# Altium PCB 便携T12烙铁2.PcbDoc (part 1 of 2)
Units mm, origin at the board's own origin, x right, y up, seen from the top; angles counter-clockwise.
Board outline 100 x 95 mm, 2 copper layers (Top Layer, Bottom Layer); 155 components, 22 nets, 605 pads, 185 vias.
Unrouted connection lines stored in the file: 84.
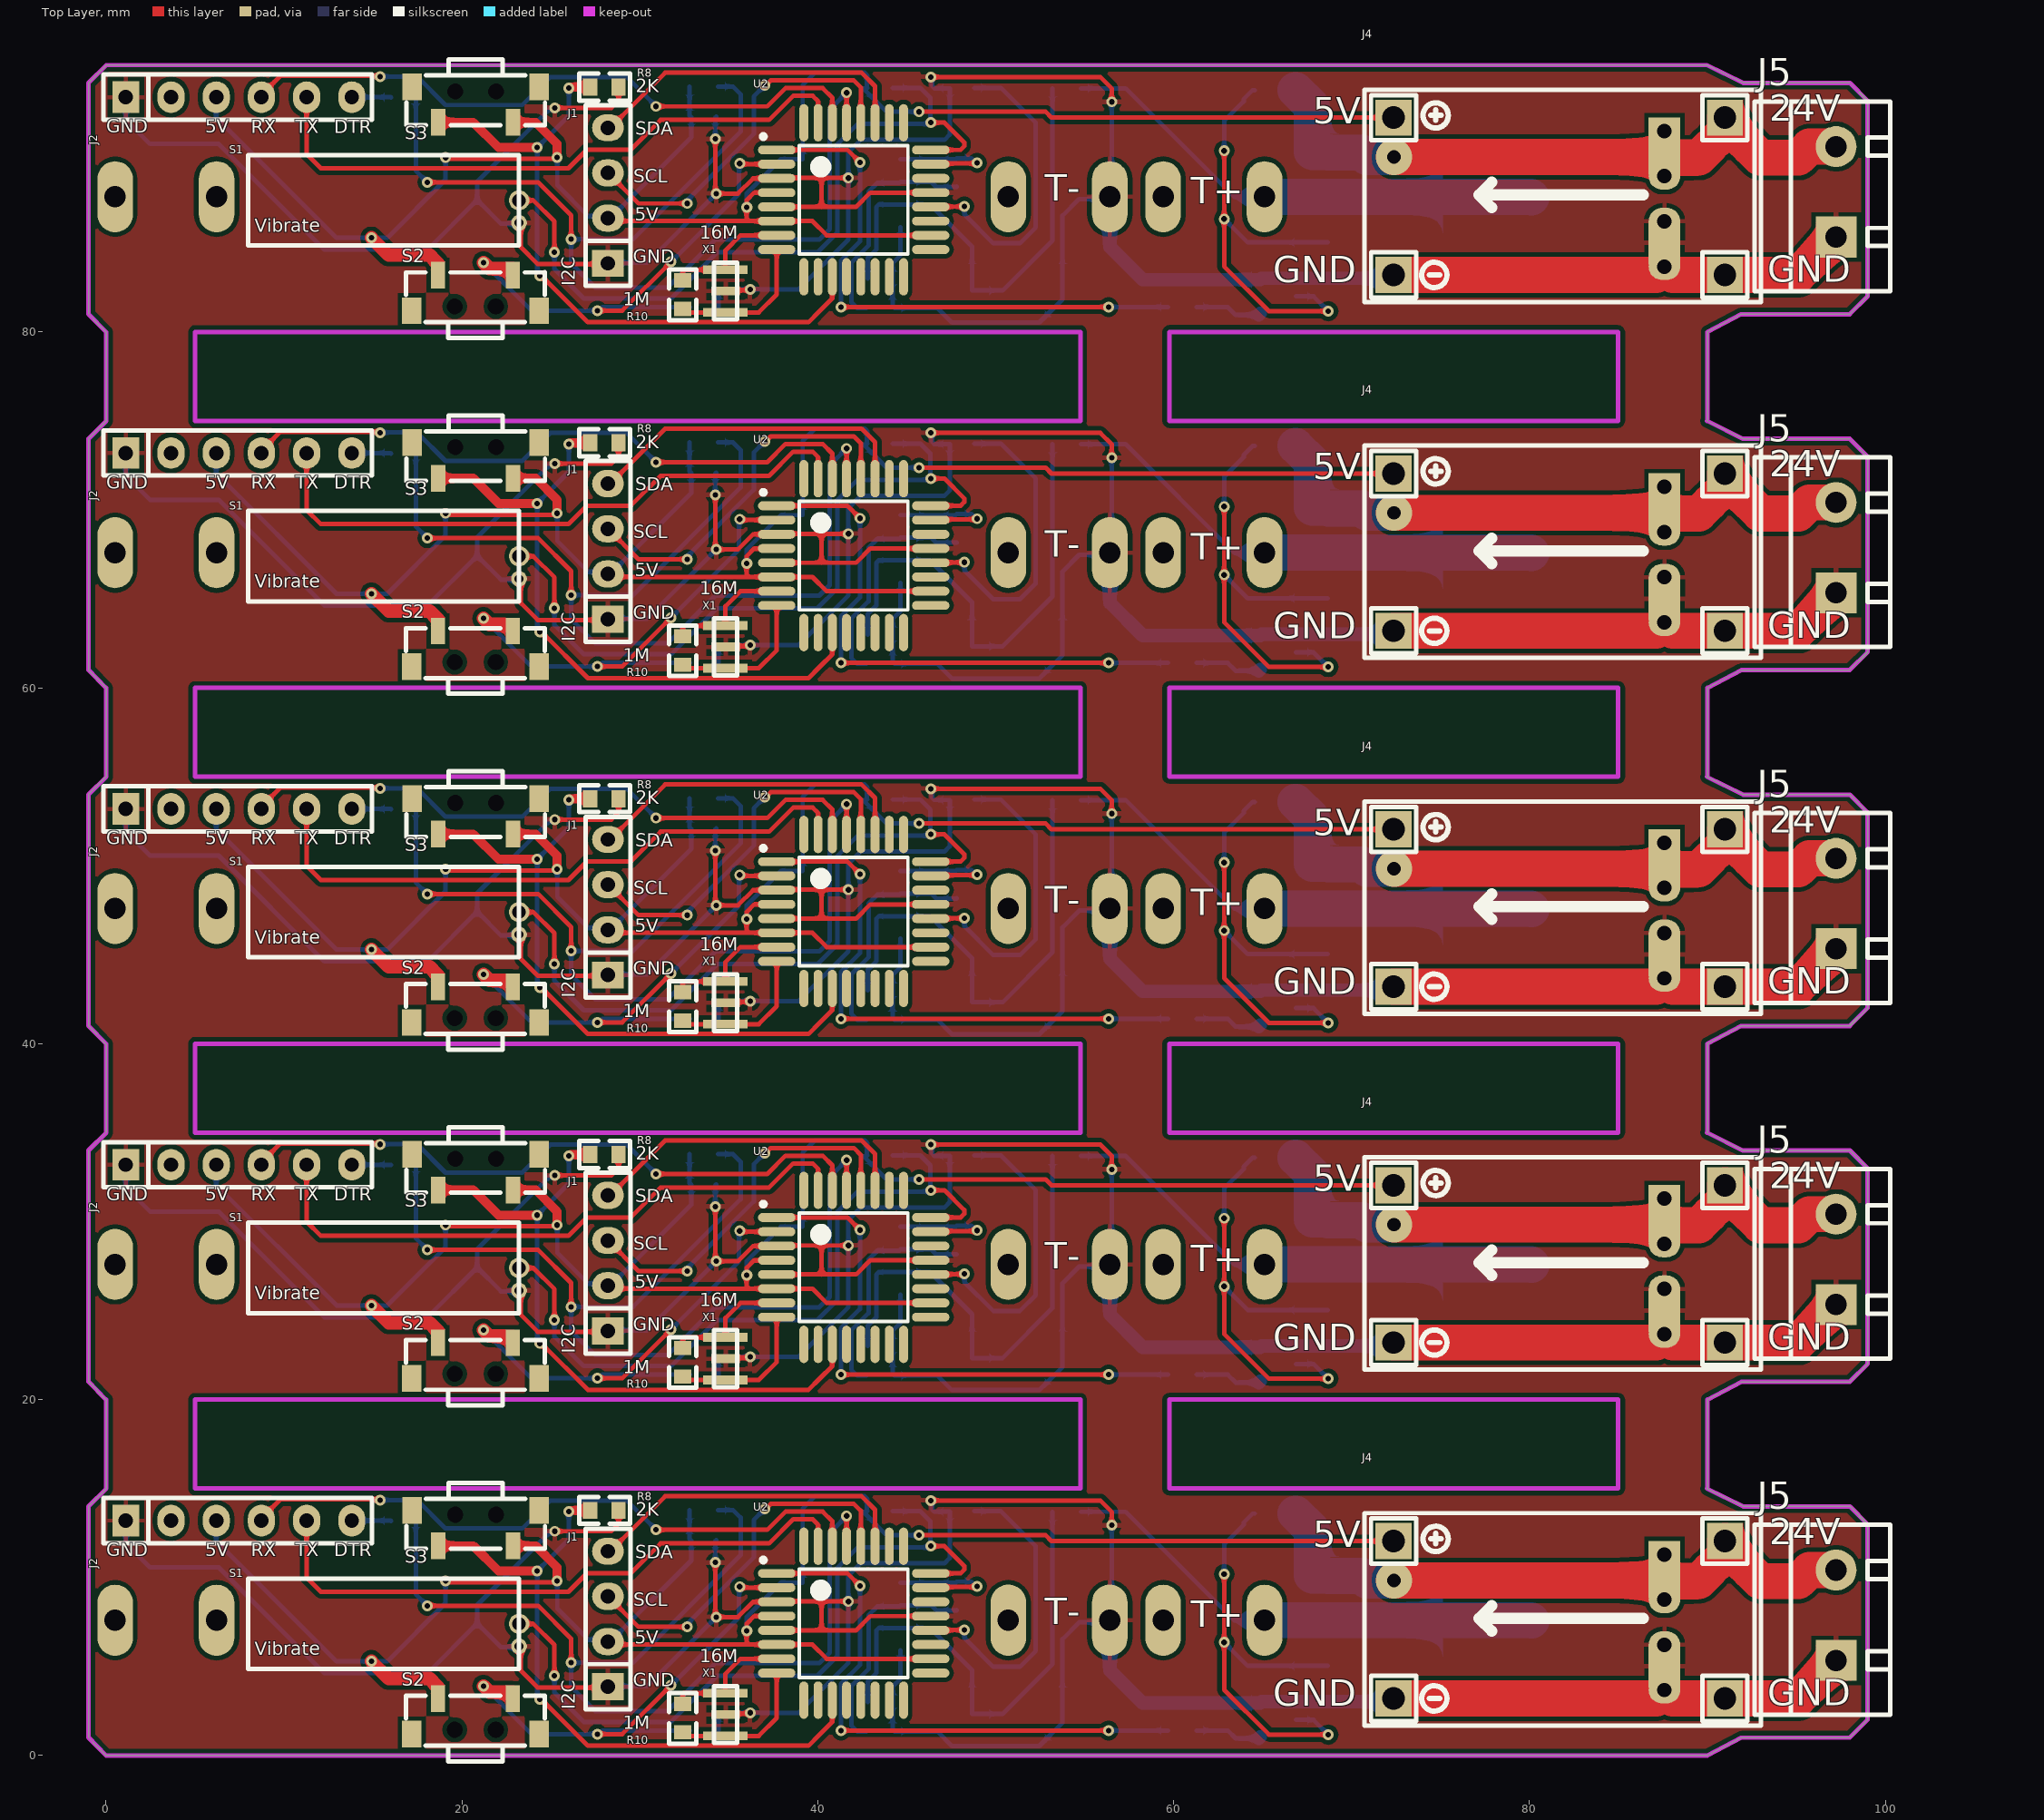
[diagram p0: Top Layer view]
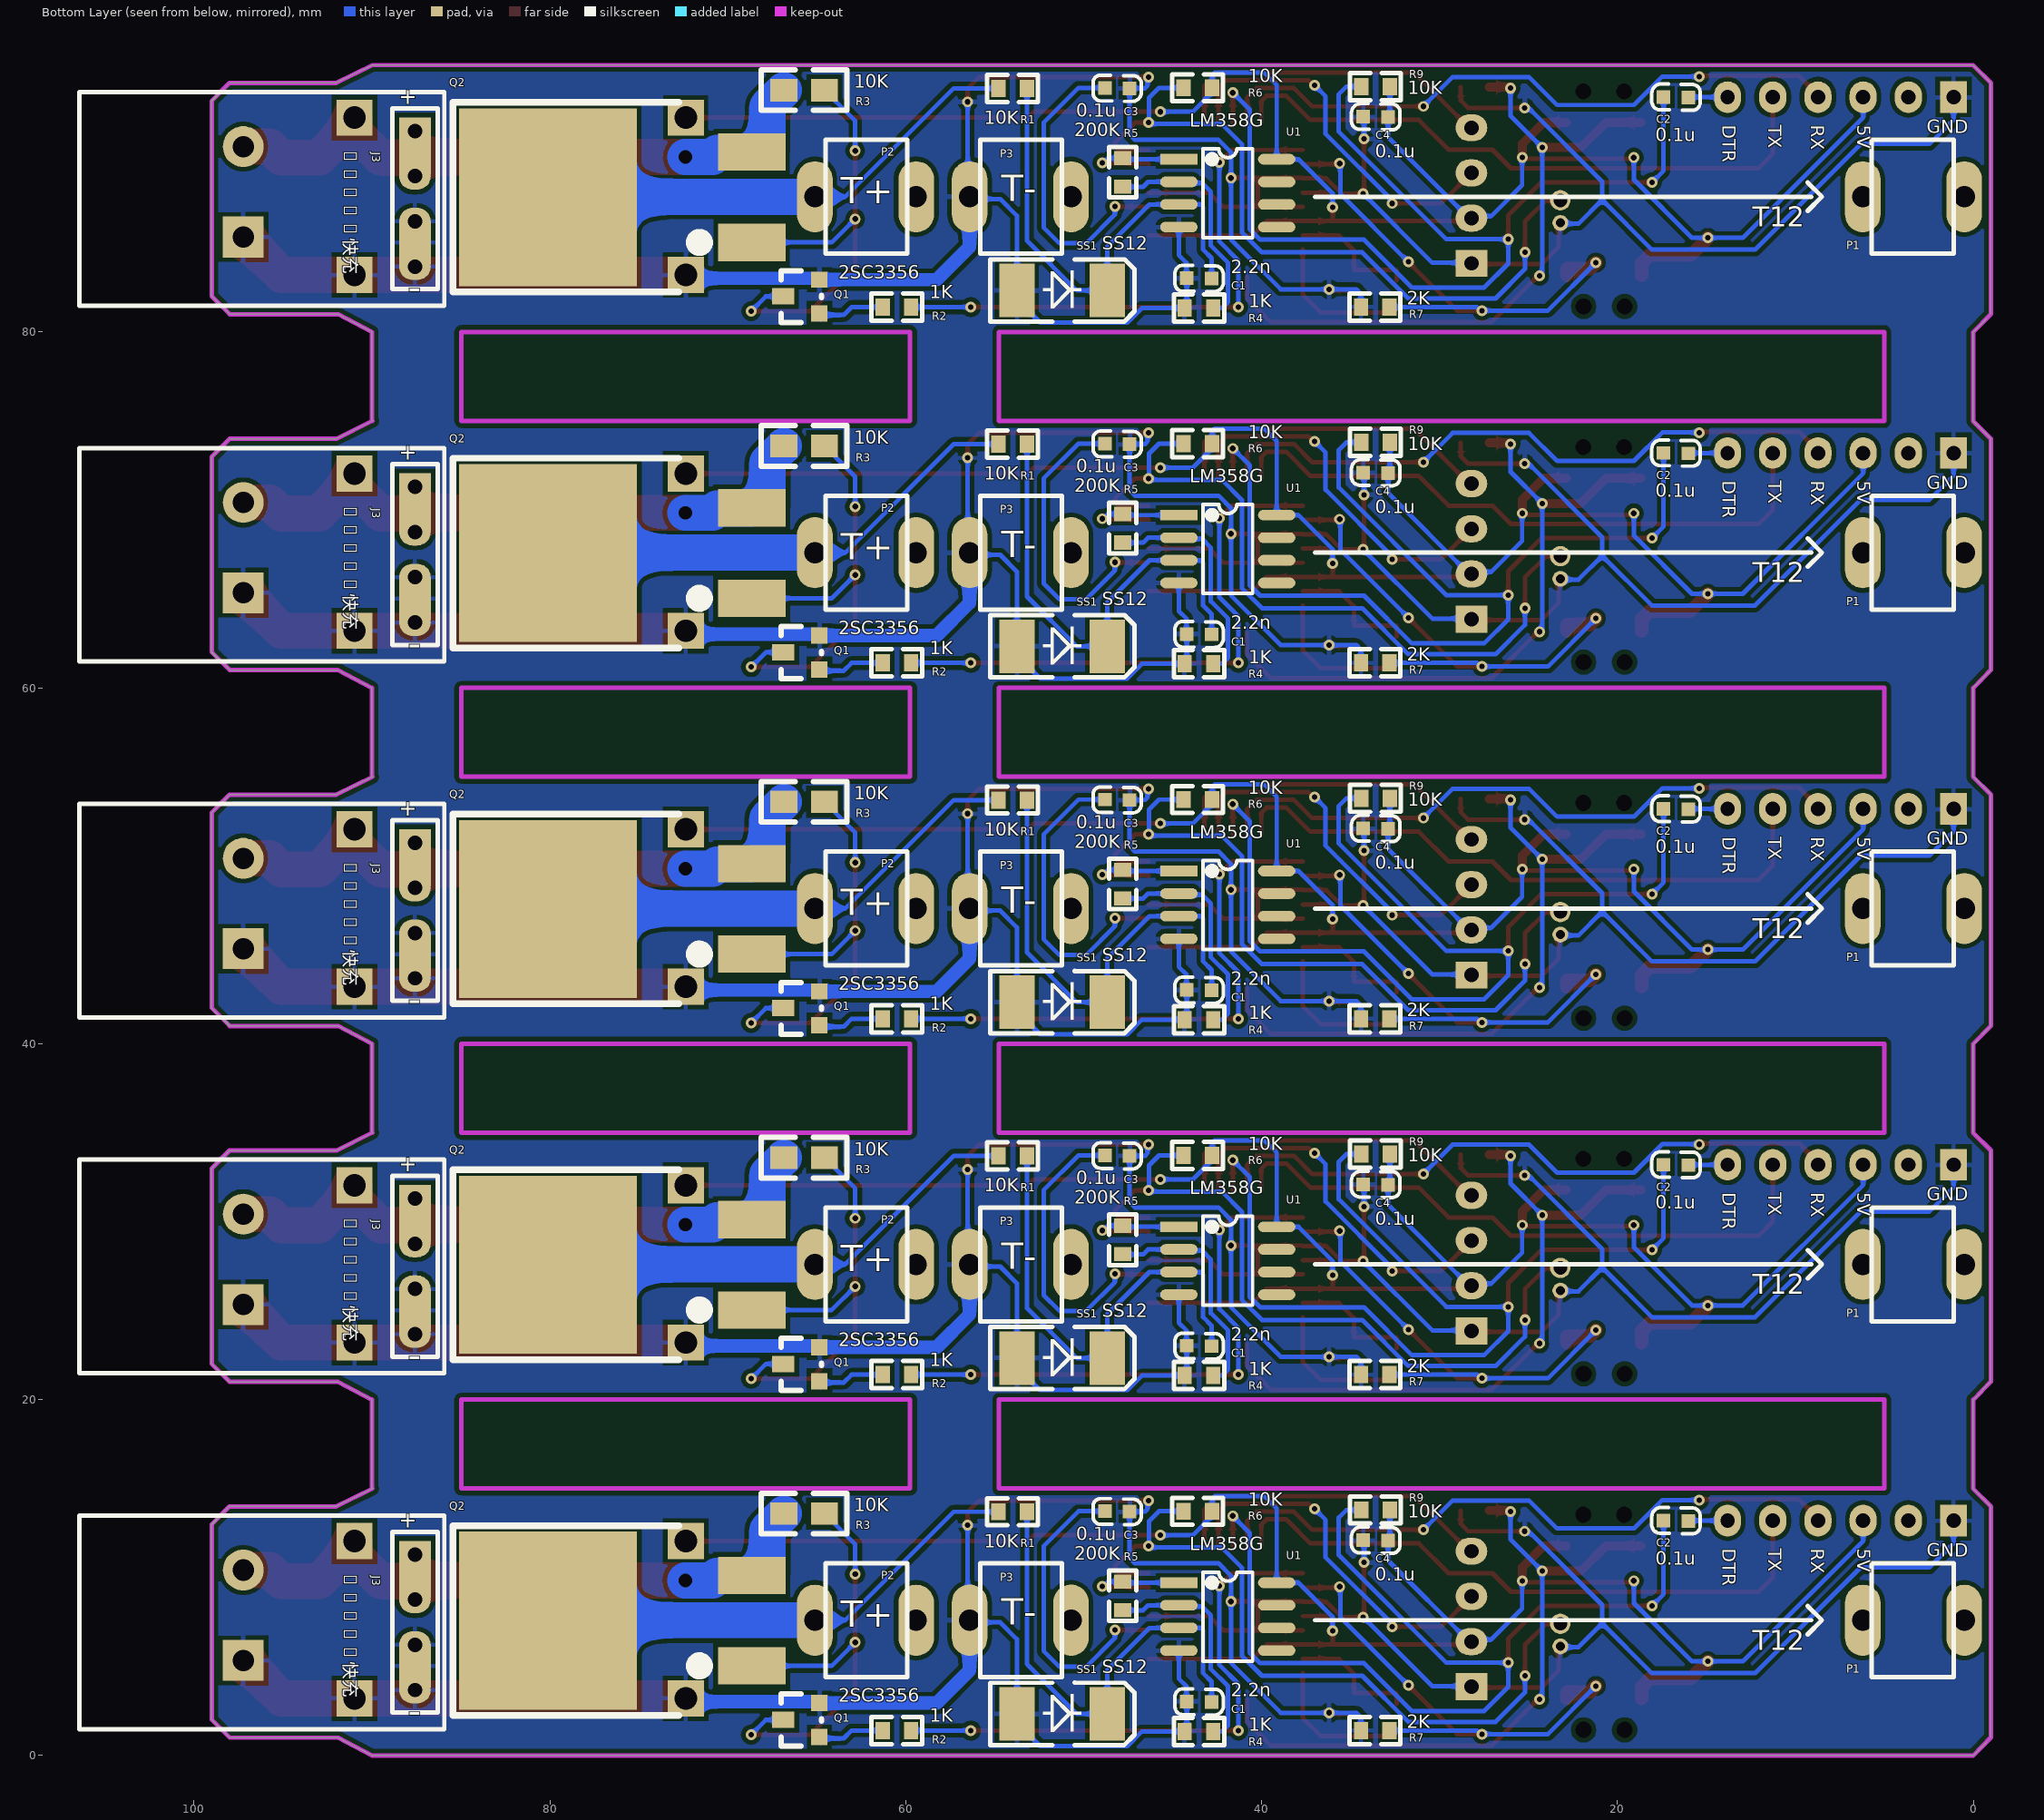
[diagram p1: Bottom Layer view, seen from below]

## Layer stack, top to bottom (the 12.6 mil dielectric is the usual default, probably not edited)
Top Solder: solder mask 0.0102, Solder Resist, Dk 3.5
Top Layer: signal copper 0.0356
Dielectric 1: dielectric 0.32, FR-4, Dk 4.8
Bottom Layer: signal copper 0.0356
Bottom Solder: solder mask 0.0102, Solder Resist, Dk 3.5

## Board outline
-0.986,1.008 0,0 90.013,0 91.915,0.998 98.003,0.998 99.014,2.012 99.014,12.984 98.008,13.998 92.014,13.998 89.98,14.999 90.013,15.032 90.013,20 91.915,20.998 98.003,20.998 99.014,22.012 99.014,32.984 98.008,33.998 92.014,33.998 89.98,34.999 90.013,35.032 90.013,40 91.915,40.998 98.003,40.998 99.014,42.012 99.014,52.984 98.008,53.998 92.014,53.998 89.98,54.999 90.013,55.032 90.013,60 91.915,60.998 98.003,60.998 99.014,62.012 99.014,72.984 98.008,73.998 92.014,73.998 89.98,74.999 90.013,75.032 90.013,80 91.915,80.998 98.003,80.998 99.014,82.012 99.014,92.984 98.008,93.998 92.014,93.998 89.98,94.999 0.015,94.999 -0.986,93.998 -0.986,81.008 0,80 0.015,79.985 0.015,74.999 -0.986,73.998 -0.986,61.008 0,60 0.015,59.985 0.015,54.999 -0.986,53.998 -0.986,41.008 0,40 0.015,39.985 0.015,34.999 -0.986,33.998 -0.986,21.008 0,20 0.015,19.985 0.015,14.999 -0.986,13.998

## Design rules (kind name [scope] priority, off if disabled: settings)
Clearance [All] p1: gap=0.254 ignorepadtopadclearanceinfootprint=FALSE except(0: Arc-Hole Track-Hole SMDPad-Hole THPad-Hole Via-Hole Fill-Hole Poly-Hole Region-Hole Text-Hole)
PolygonConnect [All] p1: connectstyle=Relief reliefconductorwidth=0.254 reliefentries=4 polygonreliefangle="90 Angle" airgapwidth=0.254
RoutingVias [All] p1: holewidth=0.711 width=1.27 viastyle="Through Hole" minholewidth=0.711 minwidth=1.27 maxholewidth=0.711 maxwidth=1.27
SolderMaskExpansion [All] p1: expansion=0.102 istentingtop=FALSE
Width [All] p1: maxlimit=0.254 minlimit=0.254 preferedwidth=0.254
30 further rules are at their usual default settings.

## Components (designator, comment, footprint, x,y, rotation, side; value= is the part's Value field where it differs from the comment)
C1 "2.2n" 0603C 44.215,83.035 r180 bottom
C1 "2.2n" 0603C 44.215,63.035 r180 bottom
C1 "2.2n" 0603C 44.215,43.035 r180 bottom
C1 "2.2n" 0603C 44.215,23.035 r180 bottom
C1 "2.2n" 0603C 44.215,3.035 r180 bottom
C2 "0.1u" 0603C 16.012,93.165 r0 bottom
C2 "0.1u" 0603C 16.012,73.165 r0 bottom
C2 "0.1u" 0603C 16.012,53.165 r0 bottom
C2 "0.1u" 0603C 16.012,33.165 r0 bottom
C2 "0.1u" 0603C 16.012,13.165 r0 bottom
C3 "0.1u" 0603C 48.822,93.731 r180 bottom
C3 "0.1u" 0603C 48.822,73.731 r180 bottom
C3 "0.1u" 0603C 48.822,53.731 r180 bottom
C3 "0.1u" 0603C 48.822,33.731 r180 bottom
C3 "0.1u" 0603C 48.822,13.731 r180 bottom
C4 "0.1u" 0603C 32.889,92.062 r0 bottom
C4 "0.1u" 0603C 32.889,72.062 r0 bottom
C4 "0.1u" 0603C 32.889,52.062 r0 bottom
C4 "0.1u" 0603C 32.889,32.062 r0 bottom
C4 "0.1u" 0603C 32.889,12.062 r0 bottom
J1 "Pin HDR1X4" "PIN HDR1X4/2.54MM-S" 28.214,83.858 r180 top
J1 "Pin HDR1X4" "PIN HDR1X4/2.54MM-S" 28.214,63.858 r180 top
J1 "Pin HDR1X4" "PIN HDR1X4/2.54MM-S" 28.214,43.858 r180 top
J1 "Pin HDR1X4" "PIN HDR1X4/2.54MM-S" 28.214,23.858 r180 top
J1 "Pin HDR1X4" "PIN HDR1X4/2.54MM-S" 28.214,3.858 r180 top
J2 "下载接口" "PIN HDR1X6/2.54MM-S" 1.115,93.198 r90 top
J2 "下载接口" "PIN HDR1X6/2.54MM-S" 1.115,73.198 r90 top
J2 "下载接口" "PIN HDR1X6/2.54MM-S" 1.115,53.198 r90 top
J2 "下载接口" "PIN HDR1X6/2.54MM-S" 1.115,33.198 r90 top
J2 "下载接口" "PIN HDR1X6/2.54MM-S" 1.115,13.198 r90 top
J3 "ip2721D快充SCH封装" IP2721D快充PCB封装 93.352,85.744 r180 bottom
J3 "ip2721D快充SCH封装" IP2721D快充PCB封装 93.352,65.744 r180 bottom
J3 "ip2721D快充SCH封装" IP2721D快充PCB封装 93.352,45.744 r180 bottom
J3 "ip2721D快充SCH封装" IP2721D快充PCB封装 93.352,25.744 r180 bottom
J3 "ip2721D快充SCH封装" IP2721D快充PCB封装 93.352,5.744 r180 bottom
J4 "Pin HDR1X2" MP1584EN稳压PCB封装 75.546,77.616 r0 top
J4 "Pin HDR1X2" MP1584EN稳压PCB封装 75.546,57.616 r0 top
J4 "Pin HDR1X2" MP1584EN稳压PCB封装 75.546,37.616 r0 top
J4 "Pin HDR1X2" MP1584EN稳压PCB封装 75.546,17.616 r0 top
J4 "Pin HDR1X2" MP1584EN稳压PCB封装 75.546,-2.384 r0 top
J5 "KF301-2P" KF301-5.0-2P 97.238,85.338 r90 top
J5 "KF301-2P" KF301-5.0-2P 97.238,65.338 r90 top
J5 "KF301-2P" KF301-5.0-2P 97.238,45.338 r90 top
J5 "KF301-2P" KF301-5.0-2P 97.238,25.338 r90 top
J5 "KF301-2P" KF301-5.0-2P 97.238,5.338 r90 top
P1 "保险丝夹子" FUSE-5X20 0.515,87.599 r180 bottom
P1 "保险丝夹子" FUSE-5X20 0.515,67.599 r180 bottom
P1 "保险丝夹子" FUSE-5X20 0.515,47.599 r180 bottom
P1 "保险丝夹子" FUSE-5X20 0.515,27.599 r180 bottom
P1 "保险丝夹子" FUSE-5X20 0.515,7.599 r180 bottom
P2 "保险丝夹子" FUSE-5X20 65.114,87.599 r0 bottom
P2 "保险丝夹子" FUSE-5X20 65.114,67.599 r0 bottom
P2 "保险丝夹子" FUSE-5X20 65.114,47.599 r0 bottom
P2 "保险丝夹子" FUSE-5X20 65.114,27.599 r0 bottom
P2 "保险丝夹子" FUSE-5X20 65.114,7.599 r0 bottom
P3 "保险丝夹子" FUSE-5X20 56.415,87.6 r0 bottom
P3 "保险丝夹子" FUSE-5X20 56.415,67.6 r0 bottom
P3 "保险丝夹子" FUSE-5X20 56.415,47.6 r0 bottom
P3 "保险丝夹子" FUSE-5X20 56.415,27.6 r0 bottom
P3 "保险丝夹子" FUSE-5X20 56.415,7.6 r0 bottom
Q1 "NPN" SOT-23 65.75,81.923 r90 bottom
Q1 "NPN" SOT-23 65.75,61.923 r90 bottom
Q1 "NPN" SOT-23 65.75,41.923 r90 bottom
Q1 "NPN" SOT-23 65.75,21.923 r90 bottom
Q1 "NPN" SOT-23 65.75,1.923 r90 bottom
Q2 "P-MOS" TO263-3B 80.113,87.573 r90 bottom
Q2 "P-MOS" TO263-3B 80.113,67.573 r90 bottom
Q2 "P-MOS" TO263-3B 80.113,47.573 r90 bottom
Q2 "P-MOS" TO263-3B 80.113,27.573 r90 bottom
Q2 "P-MOS" TO263-3B 80.113,7.573 r90 bottom
R1 "10K" 0603R 54.794,93.695 r180 bottom
R1 "10K" 0603R 54.794,73.695 r180 bottom
R1 "10K" 0603R 54.794,53.695 r180 bottom
R1 "10K" 0603R 54.794,33.695 r180 bottom
R1 "10K" 0603R 54.794,13.695 r180 bottom
R2 "1K" 0603R 61.297,81.401 r180 bottom
R2 "1K" 0603R 61.297,61.401 r180 bottom
R2 "1K" 0603R 61.297,41.401 r180 bottom
R2 "1K" 0603R 61.297,21.401 r180 bottom
R2 "1K" 0603R 61.297,1.401 r180 bottom
R3 "10K" 0805R 64.573,93.593 r0 bottom
R3 "10K" 0805R 64.573,73.593 r0 bottom
R3 "10K" 0805R 64.573,53.593 r0 bottom
R3 "10K" 0805R 64.573,33.593 r0 bottom
R3 "10K" 0805R 64.573,13.593 r0 bottom
R4 "1K" 0603R 42.73,81.35 r0 bottom
R4 "1K" 0603R 42.73,61.35 r0 bottom
R4 "1K" 0603R 42.73,41.35 r0 bottom
R4 "1K" 0603R 42.73,21.35 r0 bottom
R4 "1K" 0603R 42.73,1.35 r0 bottom
R5 "200K" 0603R 47.817,89.769 r270 bottom
R5 "200K" 0603R 47.817,69.769 r270 bottom
R5 "200K" 0603R 47.817,49.769 r270 bottom
R5 "200K" 0603R 47.817,29.769 r270 bottom
R5 "200K" 0603R 47.817,9.769 r270 bottom
R6 "10K" 0603R 44.391,93.722 r180 bottom
R6 "10K" 0603R 44.391,73.722 r180 bottom
R6 "10K" 0603R 44.391,53.722 r180 bottom
R6 "10K" 0603R 44.391,33.722 r180 bottom
R6 "10K" 0603R 44.391,13.722 r180 bottom
R7 "2K" 0603R 34.417,81.4 r180 bottom
R7 "2K" 0603R 34.417,61.4 r180 bottom
R7 "2K" 0603R 34.417,41.4 r180 bottom
R7 "2K" 0603R 34.417,21.4 r180 bottom
R7 "2K" 0603R 34.417,1.4 r180 bottom
R8 "2K" 0603R 28.81,93.771 r180 top
R8 "2K" 0603R 28.81,73.771 r180 top
R8 "2K" 0603R 28.81,53.771 r180 top
R8 "2K" 0603R 28.81,33.771 r180 top
R8 "2K" 0603R 28.81,13.771 r180 top
R9 "10K" 0603R 34.398,93.796 r180 bottom
R9 "10K" 0603R 34.398,73.796 r180 bottom
R9 "10K" 0603R 34.398,53.796 r180 bottom
R9 "10K" 0603R 34.398,33.796 r180 bottom
R9 "10K" 0603R 34.398,13.796 r180 bottom
R10 "1M" 0603R 32.415,81.298 r90 top
R10 "1M" 0603R 32.415,61.298 r90 top
R10 "1M" 0603R 32.415,41.298 r90 top
R10 "1M" 0603R 32.415,21.298 r90 top
R10 "1M" 0603R 32.415,1.298 r90 top
S1 "S" S 23.216,87.399 r90 top
S1 "S" S 23.216,67.399 r90 top
S1 "S" S 23.216,47.399 r90 top
S1 "S" S 23.216,27.399 r90 top
S1 "S" S 23.216,7.399 r90 top
S2 "SW" "TSW 3*6*4.3-S-W" 20.758,81.442 r0 top
S2 "SW" "TSW 3*6*4.3-S-W" 20.758,61.442 r0 top
S2 "SW" "TSW 3*6*4.3-S-W" 20.758,41.442 r0 top
S2 "SW" "TSW 3*6*4.3-S-W" 20.758,21.442 r0 top
S2 "SW" "TSW 3*6*4.3-S-W" 20.758,1.442 r0 top
S3 "SW" "TSW 3*6*4.3-S-W" 20.774,93.529 r180 top
S3 "SW" "TSW 3*6*4.3-S-W" 20.774,73.529 r180 top
S3 "SW" "TSW 3*6*4.3-S-W" 20.774,53.529 r180 top
S3 "SW" "TSW 3*6*4.3-S-W" 20.774,33.529 r180 top
S3 "SW" "TSW 3*6*4.3-S-W" 20.774,13.529 r180 top
SS1 "1N5819" SMA/DO-214AC 53.63,82.333 r180 bottom
SS1 "1N5819" SMA/DO-214AC 53.63,62.333 r180 bottom
SS1 "1N5819" SMA/DO-214AC 53.63,42.333 r180 bottom
SS1 "1N5819" SMA/DO-214AC 53.63,22.333 r180 bottom
SS1 "1N5819" SMA/DO-214AC 53.63,2.333 r180 bottom
U1 "LM358G-S08-R" SOP8 44.655,89.707 r180 bottom
U1 "LM358G-S08-R" SOP8 44.655,69.707 r180 bottom
U1 "LM358G-S08-R" SOP8 44.655,49.707 r180 bottom
U1 "LM358G-S08-R" SOP8 44.655,29.707 r180 bottom
U1 "LM358G-S08-R" SOP8 44.655,9.707 r180 bottom
U2 "ATMEGA328P-AU" "TQFP32 7X7_M" 42.023,87.428 r270 top
U2 "ATMEGA328P-AU" "TQFP32 7X7_M" 42.023,67.428 r270 top
U2 "ATMEGA328P-AU" "TQFP32 7X7_M" 42.023,47.428 r270 top
U2 "ATMEGA328P-AU" "TQFP32 7X7_M" 42.023,27.428 r270 top
U2 "ATMEGA328P-AU" "TQFP32 7X7_M" 42.023,7.428 r270 top
X1 "16MHZ" 晶振3213 34.816,83.498 r0 top
X1 "16MHZ" 晶振3213 34.816,63.498 r0 top
X1 "16MHZ" 晶振3213 34.816,43.498 r0 top
X1 "16MHZ" 晶振3213 34.816,23.498 r0 top
X1 "16MHZ" 晶振3213 34.816,3.498 r0 top

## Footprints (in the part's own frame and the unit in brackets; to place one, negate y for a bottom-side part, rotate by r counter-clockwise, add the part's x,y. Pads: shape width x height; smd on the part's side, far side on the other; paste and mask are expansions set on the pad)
0603C [mil] "电容"
  rect 30x30 smd: 1(0.21,-0.35) 2(55.21,-1.35)
  silkscreen extent -26,-30 81,28, body extent -1,-15 62,16, height 12
0603R [mm] "电阻"
  rect 0.8x0.965 smd: 1(0,0) 2(1.6,0)
  silkscreen extent -0.64,-0.76 2.21,0.76, body extent -0.04,-0.41 1.56,0.41, height 0.45
0805R [mil] "电阻"
  rect 60x50 smd: 1(0,0) 2(90,0)
  silkscreen extent -50,-45 140,45, body extent 1,-25 80,25, height 15
FUSE-5X20 [mm] "保险丝夹子"
  oval 2x4 hole 1.2: 1(0,0) 2(-5.7,0)
  silkscreen extent -5.2,-3.2 -0.6,3.2
IP2721D快充PCB封装 [mil]
  oval 70x60 hole 32: 1(226.84,118.59) 2(226.84,-81.41) 2(226.84,18.59)
  rrect50% 70x110 all layers, no hole: 1(226.84,159.59)
  rect 70x60 hole 32: 1(226.84,218.59)
  rrect50% 70x130 all layers, no hole: 2(226.84,-28.41)
  silkscreen extent -515,-168 292,305, body extent 177,-131 277,269, height 336
KF301-5.0-2P [mm] "可拼接端子/6A"
  rect 2.3x2.3 hole 1.2: 1(0,0)
  round 2.3 hole 1.2: 2(5.08,0)
  silkscreen extent -3.05,-3.05 7.62,4.57, body extent -3,-3.09 7.5,4.51, height 10.05
MP1584EN稳压PCB封装 [mil]
  rect 80x80 hole 50: IN+(608,568) IN-(608,220) OUT+(-125,568) OUT-(-125,220)
  silkscreen extent -190,160 688,630, body extent -175,70 658,718, height 336
"PIN HDR1X4/2.54MM-S" [mil] "0.91 i2c oled"
  rect 70x60 hole 32: 1(0,0)
  oval 70x60 hole 32: 2(0,-100) 3(0,-200) 4(0,-300)
  silkscreen extent -50,-350 50,50, body extent -50,-350 50,50, height 336
"PIN HDR1X6/2.54MM-S" [mil] "下载接口"
  rect 70x60 hole 32: 1(0,0)
  oval 70x60 hole 32: 2(0,-100) 3(0,-200) 4(0,-300) 5(0,-400) 6(0,-500)
  silkscreen extent -50,-545 50,50, body extent -50,-545 50,55, height 336
S [mil] "震动开关"
  round 45 hole 30: 1(0,0)
  round 35 hole 20: 2(-50,0)
  silkscreen extent -100,0 100,600, body extent -69,-5 49,396, height 119
SMA/DO-214AC [mm] "塑封二极管"
  rect 2x3 smd: A(-0.127,0) K(4.953,0)
  silkscreen extent -1.63,-1.75 6.48,1.75, body extent 0.11,-1.35 4.71,1.35, height 2.4
SOP8 [mm] "LM358G-S08-R"
  rect 2.1x0.6 smd: 1(0,0)
  oval 2.1x0.6 smd: 2(0,-1.27) 3(0,-2.54) 4(0,-3.81) 5(5.5,-3.81) 6(5.5,-2.54) 7(5.5,-1.27) 8(5.5,0)
  silkscreen extent 1.35,-4.41 4.15,0.6, body extent -0.21,-4.4 5.8,0.6, height 1.9
SOT-23 [mil] "三极管"
  rect 36x36 smd: B(-35,-35) E(40,-35)
  rect 36x50 smd: C(3,45)
  silkscreen extent -55,-40 60,50, body extent -54,-48 60,62, height 47
TO263-3B [mm] "P-MOS"
  rect 10x10 smd: D(0,0)
  rect 2.1x3.8 smd: G(-2.54,-11.45) S(2.54,-11.45)
  silkscreen extent -5.33,-8.89 5.33,5.33, body extent -4.92,-11.05 5.08,3.88, height 4.5
"TQFP32 7X7_M" [mm] "32脚，体宽：7x7mm, 脚距：0.8mm ATMEGA328P-AU"
  oval 0.5x2.1 smd: 1(-2.803,-4.327) 2(-2.003,-4.327) 3(-1.203,-4.327) 4(-0.403,-4.327) 5(0.397,-4.327) 6(1.197,-4.327) 7(1.997,-4.327) 8(2.797,-4.327) 17(2.797,4.327) 18(1.997,4.327) 19(1.197,4.327) 20(0.397,4.327) 21(-0.403,4.327) 22(-1.203,4.327) 23(-2.003,4.327) 24(-2.803,4.327)
  oval 2.1x0.5 smd: 9(4.324,-2.8) 10(4.324,-2) 11(4.324,-1.2) 12(4.324,-0.4) 13(4.324,0.4) 14(4.324,1.2) 15(4.324,2) 16(4.324,2.8) 25(-4.33,2.8) 26(-4.33,2) 27(-4.33,1.2) 28(-4.33,0.4) 29(-4.33,-0.4) 30(-4.33,-1.2) 31(-4.33,-2) 32(-4.33,-2.8)
  silkscreen extent -3.68,-5.2 3.05,3.05, body extent -4.5,-4.5 4.5,4.5, height 1.05
"TSW 3*6*4.3-S-W" [mm] "侧立贴片3*6*4.3"
  rect 1.1x1.5 smd: 0(-3.575,-0.25) 0(3.575,-0.25)
  round 0 hole 0.9: 0(-1.15,0) 0(1.15,0)
  rect 0.8x1.5 smd: 1(-2.1,1.75) 2(2.1,1.75)
  silkscreen extent -3.9,-1.78 3.9,1.91, body extent -3.9,-1.79 3.9,1.91, height 3.51
晶振3213 [mil] "晶振3213"
  rect 98.5x19.6 smd: 1(0,0) 3(0,-94.4)
  rect 63x19.6 smd: 2(-0.05,-47.2)
  silkscreen extent -26,-110 26,16, body extent -30,-110 29,16, height 24

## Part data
C1 C1 C1 C1 C1 C2 C2 C2 C2 C2 C3 C3 C3 C3 C3 C4 C4 C4 C4 C4: library part CAP, "无极性电容"
J1 J1 J1 J1 J1: "0.91 i2c oled"
J2 J2 J2 J2 J2: library part "Pin HDR1X6"
J4 J4 J4 J4 J4: library part MP1584EN稳压SCH封装
Q1 Q1 Q1 Q1 Q1: "NPN三极管 / 2SC3356-T1B-A"
Q2 Q2 Q2 Q2 Q2: "P沟道场效应管 / IRF4905STRLPBF"
R1 R1 R1 R1 R1 R2 R2 R2 R2 R2 R3 R3 R3 R3 R3 R4 R4 R4 R4 R4 R5 R5 R5 R5 R5 R6 R6 R6 R6 R6 R7 R7 R7 R7 R7 R8 R8 R8 R8 R8 R9 R9 R9 R9 R9 R10 R10 R10 R10 R10: library part RES, "电阻"
S1 S1 S1 S1 S1: "震动开关 / SW180  建议SW18015"
S2 S2 S2 S2 S2 S3 S3 S3 S3 S3: "侧立按键开关 / 3*6*4.3"
SS1 SS1 SS1 SS1 SS1: library part "DIODE SCHOTTKY", "肖特基二极管SS12"
U1 U1 U1 U1 U1: "运放"
X1 X1 X1 X1 X1: library part 晶振3213, "晶振3213"

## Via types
v1: diameter 0.61, hole 0.31, Top Layer to Bottom Layer, 120 vias
v2: diameter 0.62, hole 0.305, Top Layer to Bottom Layer, 30 vias
v3: diameter 0.61, hole 0.33, Top Layer to Bottom Layer, 20 vias
v4: diameter 0.61/0.61 (per signal layer), hole 0.33, Top Layer to Bottom Layer, 10 vias
v5: diameter 2.032/0.61 (per signal layer), hole 0.762, Top Layer to Bottom Layer, 5 vias

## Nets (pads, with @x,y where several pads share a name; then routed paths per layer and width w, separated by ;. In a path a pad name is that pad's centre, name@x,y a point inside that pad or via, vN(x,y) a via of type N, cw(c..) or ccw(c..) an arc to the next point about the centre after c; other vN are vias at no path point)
5V: C4.1 J1.2 J2.3 J4.OUT+ R6.2 R9.2 S2.1 S3.1 U1.8 U2.4 U2.6 U2.18 | length 574.3
  Top Layer w0.254: v3(19.082,9.808) 19.158,9.732 25.279,9.732 v1(25.356,9.809) ; v3(19.082,29.808) 19.158,29.732 25.279,29.732 v1(25.356,29.809) ; v3(19.082,49.808) 19.158,49.732 25.279,49.732 v1(25.356,49.809) ; v3(19.082,69.808) 19.158,69.732 25.279,69.732 v1(25.356,69.809) ; v3(19.082,89.808) 19.158,89.732 25.279,89.732 v1(25.356,89.809) ; J1.2@28.214,6.398 28.382,6.231 36.165,6.231 ; J1.2@28.214,26.398 28.382,26.231 36.165,26.231 ; J1.2@28.214,46.398 28.382,46.231 36.165,46.231 ; J1.2@28.214,66.398 28.382,66.231 36.165,66.231 ; J1.2@28.214,86.398 28.382,86.231 36.165,86.231 ; U2.4@37.696,7.831 36.434,7.831 36.016,7.413 v2(36.016,6.999) 35.997,6.98 35.997,6.398 36.165,6.231 ; U2.4@37.696,27.831 36.434,27.831 36.016,27.413 v2(36.016,26.999) 35.997,26.98 35.997,26.398 36.165,26.231 ; U2.4@37.696,47.831 36.434,47.831 36.016,47.413 v2(36.016,46.999) 35.997,46.98 35.997,46.398 36.165,46.231 ; U2.4@37.696,67.831 36.434,67.831 36.016,67.413 v2(36.016,66.999) 35.997,66.98 35.997,66.398 36.165,66.231 ; U2.4@37.696,87.831 36.434,87.831 36.016,87.413 v2(36.016,86.999) 35.997,86.98 35.997,86.398 36.165,86.231 ; v1(45.686,12.374) 52.813,12.374 53.143,12.044 J4.OUT+@72.371,12.044 ; v1(45.686,32.374) 52.813,32.374 53.143,32.044 J4.OUT+@72.371,32.044 ; v1(45.686,52.374) 52.813,52.374 53.143,52.044 J4.OUT+@72.371,52.044 ; v1(45.686,72.374) 52.813,72.374 53.143,72.044 J4.OUT+@72.371,72.044 ; v1(45.686,92.374) 52.813,92.374 53.143,92.044 J4.OUT+@72.371,92.044 ; U2.18@46.35,5.431 40.503,5.431 39.703,6.231 U2.6@37.696,6.231 36.165,6.231 ; U2.18@46.35,25.431 40.503,25.431 39.703,26.231 U2.6@37.696,26.231 36.165,26.231 ; U2.18@46.35,45.431 40.503,45.431 39.703,46.231 U2.6@37.696,46.231 36.165,46.231 ; U2.18@46.35,65.431 40.503,65.431 39.703,66.231 U2.6@37.696,66.231 36.165,66.231 ; U2.18@46.35,85.431 40.503,85.431 39.703,86.231 U2.6@37.696,86.231 36.165,86.231
  Top Layer w0.508: S3.1@22.874,11.779 24.148,11.779 25.356,10.571 v1(25.356,9.809) ; S3.1@22.874,31.779 24.148,31.779 25.356,30.571 v1(25.356,29.809) ; S3.1@22.874,51.779 24.148,51.779 25.356,50.571 v1(25.356,49.809) ; S3.1@22.874,71.779 24.148,71.779 25.356,70.571 v1(25.356,69.809) ; S3.1@22.874,91.779 24.148,91.779 25.356,90.571 v1(25.356,89.809)
  Top Layer w0.762: v1(14.916,5.287) 15.881,4.323 18.192,4.323 18.639,3.877 18.639,3.211 S2.1@18.658,3.192 ; v1(14.916,25.287) 15.881,24.323 18.192,24.323 18.639,23.877 18.639,23.211 S2.1@18.658,23.192 ; v1(14.916,45.287) 15.881,44.323 18.192,44.323 18.639,43.877 18.639,43.211 S2.1@18.658,43.192 ; v1(14.916,65.287) 15.881,64.323 18.192,64.323 18.639,63.877 18.639,63.211 S2.1@18.658,63.192 ; v1(14.916,85.287) 15.881,84.323 18.192,84.323 18.639,83.877 18.639,83.211 S2.1@18.658,83.192
  Bottom Layer w0.254: J2.3@6.195,13.198 6.195,12.053 12.961,5.287 v1(14.916,5.287) 15.811,5.287 19.082,8.558 v3(19.082,9.808) ; J2.3@6.195,33.198 6.195,32.053 12.961,25.287 v1(14.916,25.287) 15.811,25.287 19.082,28.558 v3(19.082,29.808) ; J2.3@6.195,53.198 6.195,52.053 12.961,45.287 v1(14.916,45.287) 15.811,45.287 19.082,48.558 v3(19.082,49.808) ; J2.3@6.195,73.198 6.195,72.053 12.961,65.287 v1(14.916,65.287) 15.811,65.287 19.082,68.558 v3(19.082,69.808) ; J2.3@6.195,93.198 6.195,92.053 12.961,85.287 v1(14.916,85.287) 15.811,85.287 19.082,88.558 v3(19.082,89.808) ; v1(25.356,9.809) 25.363,9.801 25.363,8.252 27.098,6.517 28.095,6.517 J1.2@28.214,6.398 28.341,6.398 32.894,10.951 C4.1@32.894,12.071 32.798,12.167 R9.2@32.798,13.796 ; v1(25.356,29.809) 25.363,29.801 25.363,28.252 27.098,26.517 28.095,26.517 J1.2@28.214,26.398 28.341,26.398 32.894,30.951 C4.1@32.894,32.071 32.798,32.167 R9.2@32.798,33.796 ; v1(25.356,49.809) 25.363,49.801 25.363,48.252 27.098,46.517 28.095,46.517 J1.2@28.214,46.398 28.341,46.398 32.894,50.951 C4.1@32.894,52.071 32.798,52.167 R9.2@32.798,53.796 ; v1(25.356,69.809) 25.363,69.801 25.363,68.252 27.098,66.517 28.095,66.517 J1.2@28.214,66.398 28.341,66.398 32.894,70.951 C4.1@32.894,72.071 32.798,72.167 R9.2@32.798,73.796 ; v1(25.356,89.809) 25.363,89.801 25.363,88.252 27.098,86.517 28.095,86.517 J1.2@28.214,86.398 28.341,86.398 32.894,90.951 C4.1@32.894,92.071 32.798,92.167 R9.2@32.798,93.796 ; v2(36.016,6.999) 36.016,7.794 37.929,9.707 U1.8@39.155,9.707 39.155,13.88 39.842,14.567 42.645,14.567 42.774,14.437 42.774,13.739 R6.2@42.791,13.722 ; v2(36.016,26.999) 36.016,27.794 37.929,29.707 U1.8@39.155,29.707 39.155,33.88 39.842,34.567 42.645,34.567 42.774,34.437 42.774,33.739 R6.2@42.791,33.722 ; v2(36.016,46.999) 36.016,47.794 37.929,49.707 U1.8@39.155,49.707 39.155,53.88 39.842,54.567 42.645,54.567 42.774,54.437 42.774,53.739 R6.2@42.791,53.722 ; v2(36.016,66.999) 36.016,67.794 37.929,69.707 U1.8@39.155,69.707 39.155,73.88 39.842,74.567 42.645,74.567 42.774,74.437 42.774,73.739 R6.2@42.791,73.722 ; v2(36.016,86.999) 36.016,87.794 37.929,89.707 U1.8@39.155,89.707 39.155,93.88 39.842,94.567 42.645,94.567 42.774,94.437 42.774,93.739 R6.2@42.791,93.722 ; R6.2@42.574,13.68 43.88,12.374 v1(45.686,12.374) ; R6.2@42.574,33.68 43.88,32.374 v1(45.686,32.374) ; R6.2@42.574,53.68 43.88,52.374 v1(45.686,52.374) ; R6.2@42.574,73.68 43.88,72.374 v1(45.686,72.374) ; R6.2@42.574,93.68 43.88,92.374 v1(45.686,92.374)
DTR: C2.1 J2.6 | length 11.1
  Bottom Layer w0.254: J2.6@13.815,13.198 15.993,13.198 C2.1@16.017,13.174 ; J2.6@13.815,33.198 15.993,33.198 C2.1@16.017,33.174 ; J2.6@13.815,53.198 15.993,53.198 C2.1@16.017,53.174 ; J2.6@13.815,73.198 15.993,73.198 C2.1@16.017,73.174 ; J2.6@13.815,93.198 15.993,93.198 C2.1@16.017,93.174
GND: C1.1 C3.2 C4.2 J1.1 J2.1 J3.2 J4.IN- J4.OUT- J5.1 P3.1 Q1.E R4.2 R7.1 R8.1 S1.2 SS1.A U1.4 U2.3 U2.5 U2.21 X1.2 | length 940.6
  Top Layer w0.254: S1.2@23.216,6.129 23.318,6.026 23.318,4.759 24.264,3.814 28.17,3.814 J1.1@28.214,3.858 ; S1.2@23.216,26.129 23.318,26.026 23.318,24.759 24.264,23.814 28.17,23.814 J1.1@28.214,23.858 ; S1.2@23.216,46.129 23.318,46.026 23.318,44.759 24.264,43.814 28.17,43.814 J1.1@28.214,43.858 ; S1.2@23.216,66.129 23.318,66.026 23.318,64.759 24.264,63.814 28.17,63.814 J1.1@28.214,63.858 ; S1.2@23.216,86.129 23.318,86.026 23.318,84.759 24.264,83.814 28.17,83.814 J1.1@28.214,83.858 ; v1(25.216,12.599) 28.4,12.599 28.81,13.009 R8.1@28.81,13.771 ; v1(25.216,32.599) 28.4,32.599 28.81,33.009 R8.1@28.81,33.771 ; v1(25.216,52.599) 28.4,52.599 28.81,53.009 R8.1@28.81,53.771 ; v1(25.216,72.599) 28.4,72.599 28.81,73.009 R8.1@28.81,73.771 ; v1(25.216,92.599) 28.4,92.599 28.81,93.009 R8.1@28.81,93.771 ; v1(34.246,10.85) 34.246,7.827 v1@34.347,7.827 ; v1(34.246,30.85) 34.246,27.827 v1@34.347,27.827 ; v1(34.246,50.85) 34.246,47.827 v1@34.347,47.827 ; v1(34.246,70.85) 34.246,67.827 v1@34.347,67.827 ; v1(34.246,90.85) 34.246,87.827 v1@34.347,87.827 ; v1(34.297,7.776) 35.516,7.776 36.37,8.631 U2.3@37.696,8.631 37.726,8.661 40.215,8.661 ; v1(34.297,27.776) 35.516,27.776 36.37,28.631 U2.3@37.696,28.631 37.726,28.661 40.215,28.661 ; v1(34.297,47.776) 35.516,47.776 36.37,48.631 U2.3@37.696,48.631 37.726,48.661 40.215,48.661 ; v1(34.297,67.776) 35.516,67.776 36.37,68.631 U2.3@37.696,68.631 37.726,68.661 40.215,68.661 ; v1(34.297,87.776) 35.516,87.776 36.37,88.631 U2.3@37.696,88.631 37.726,88.661 40.215,88.661 ; X1.2@34.815,2.299 34.865,2.349 36.151,2.349 v1(36.201,2.399) ; X1.2@34.815,22.299 34.865,22.349 36.151,22.349 v1(36.201,22.399) ; X1.2@34.815,42.299 34.865,42.349 36.151,42.349 v1(36.201,42.399) ; X1.2@34.815,62.299 34.865,62.349 36.151,62.349 v1(36.201,62.399) ; X1.2@34.815,82.299 34.865,82.349 36.151,82.349 v1(36.201,82.399) ; U2.5@37.696,7.031 40.215,7.031 ; U2.5@37.696,27.031 40.215,27.031 ; U2.5@37.696,47.031 40.215,47.031 ; U2.5@37.696,67.031 40.215,67.031 ; U2.5@37.696,87.031 40.215,87.031 ; v3(41.726,8.653) 41.718,8.661 40.215,8.661 ; v3(41.726,28.653) 41.718,28.661 40.215,28.661 ; v3(41.726,48.653) 41.718,48.661 40.215,48.661 ; v3(41.726,68.653) 41.718,68.661 40.215,68.661 ; v3(41.726,88.653) 41.718,88.661 40.215,88.661 ; U2.21@46.35,7.831 42.962,7.831 42.162,7.031 40.215,7.031 ; U2.21@46.35,27.831 42.962,27.831 42.162,27.031 40.215,27.031 ; U2.21@46.35,47.831 42.962,47.831 42.162,47.031 40.215,47.031 ; U2.21@46.35,67.831 42.962,67.831 42.162,67.031 40.215,67.031 ; U2.21@46.35,87.831 42.962,87.831 42.162,87.031 40.215,87.031 ; v1(46.354,14.329) 55.887,14.329 56.522,13.695 v1(56.522,12.933) ; v1(46.354,34.329) 55.887,34.329 56.522,33.695 v1(56.522,32.933) ; v1(46.354,54.329) 55.887,54.329 56.522,53.695 v1(56.522,52.933) ; v1(46.354,74.329) 55.887,74.329 56.522,73.695 v1(56.522,72.933) ; v1(46.354,94.329) 55.887,94.329 56.522,93.695 v1(56.522,92.933) ; 40.215,7.031 40.215,8.661 ; 40.215,27.031 40.215,28.661 ; 40.215,47.031 40.215,48.661 ; 40.215,67.031 40.215,68.661 ; 40.215,87.031 40.215,88.661
  Top Layer w2.032: J4.OUT-@72.371,3.204 87.118,3.204 J3.2@87.59,3.677 88.062,3.204 95.104,3.204 J5.1@97.238,5.338 ; J4.OUT-@72.371,23.204 87.118,23.204 J3.2@87.59,23.677 88.062,23.204 95.104,23.204 J5.1@97.238,25.338 ; J4.OUT-@72.371,43.204 87.118,43.204 J3.2@87.59,43.677 88.062,43.204 95.104,43.204 J5.1@97.238,45.338 ; J4.OUT-@72.371,63.204 87.118,63.204 J3.2@87.59,63.677 88.062,63.204 95.104,63.204 J5.1@97.238,65.338 ; J4.OUT-@72.371,83.204 87.118,83.204 J3.2@87.59,83.677 88.062,83.204 95.104,83.204 J5.1@97.238,85.338
  Bottom Layer w0.254: J2.1@1.115,13.198 1.115,11.926 2.47,10.57 6.331,10.57 12.275,4.627 18.066,4.627 20.86,7.421 ; J2.1@1.115,33.198 1.115,31.926 2.47,30.57 6.331,30.57 12.275,24.627 18.066,24.627 20.86,27.421 ; J2.1@1.115,53.198 1.115,51.926 2.47,50.57 6.331,50.57 12.275,44.627 18.066,44.627 20.86,47.421 ; J2.1@1.115,73.198 1.115,71.926 2.47,70.57 6.331,70.57 12.275,64.627 18.066,64.627 20.86,67.421 ; J2.1@1.115,93.198 1.115,91.926 2.47,90.57 6.331,90.57 12.275,84.627 18.066,84.627 20.86,87.421 ; S1.2@23.216,6.129 23.167,6.081 22.2,6.081 20.86,7.421 ; S1.2@23.216,26.129 23.167,26.081 22.2,26.081 20.86,27.421 ; S1.2@23.216,46.129 23.167,46.081 22.2,46.081 20.86,47.421 ; S1.2@23.216,66.129 23.167,66.081 22.2,66.081 20.86,67.421 ; S1.2@23.216,86.129 23.167,86.081 22.2,86.081 20.86,87.421 ; v1(25.216,12.599) 25.147,12.531 24.937,12.531 20.86,8.454 20.86,7.421 ; v1(25.216,32.599) 25.147,32.531 24.937,32.531 20.86,28.454 20.86,27.421 ; v1(25.216,52.599) 25.147,52.531 24.937,52.531 20.86,48.454 20.86,47.421 ; v1(25.216,72.599) 25.147,72.531 24.937,72.531 20.86,68.454 20.86,67.421 ; v1(25.216,92.599) 25.147,92.531 24.937,92.531 20.86,88.454 20.86,87.421 ; J1.1@28.214,3.858 28.247,3.89 30.411,3.89 v1(34.297,7.776) ; J1.1@28.214,23.858 28.247,23.89 30.411,23.89 v1(34.297,27.776) ; J1.1@28.214,43.858 28.247,43.89 30.411,43.89 v1(34.297,47.776) ; J1.1@28.214,63.858 28.247,63.89 30.411,63.89 v1(34.297,67.776) ; J1.1@28.214,83.858 28.247,83.89 30.411,83.89 v1(34.297,87.776) ; v1(34.246,10.85) 34.246,12.051 C4.2@34.291,12.097 ; v1(34.246,30.85) 34.246,32.051 C4.2@34.291,32.097 ; v1(34.246,50.85) 34.246,52.051 C4.2@34.291,52.097 ; v1(34.246,70.85) 34.246,72.051 C4.2@34.291,72.097 ; v1(34.246,90.85) 34.246,92.051 C4.2@34.291,92.097 ; R7.1@34.417,1.4 34.424,1.406 34.424,2.138 34.685,2.399 v1(36.201,2.399) 38.927,2.399 41.726,5.198 41.726,10.101 42.425,10.799 47.127,10.799 47.419,11.091 C3.2@47.419,13.697 46.563,13.697 46.422,13.838 46.422,14.261 v1(46.354,14.329) ; R7.1@34.417,21.4 34.424,21.406 34.424,22.138 34.685,22.399 v1(36.201,22.399) 38.927,22.399 41.726,25.198 41.726,30.101 42.425,30.799 47.127,30.799 47.419,31.091 C3.2@47.419,33.697 46.563,33.697 46.422,33.838 46.422,34.261 v1(46.354,34.329) ; R7.1@34.417,41.4 34.424,41.406 34.424,42.138 34.685,42.399 v1(36.201,42.399) 38.927,42.399 41.726,45.198 41.726,50.101 42.425,50.799 47.127,50.799 47.419,51.091 C3.2@47.419,53.697 46.563,53.697 46.422,53.838 46.422,54.261 v1(46.354,54.329) ; R7.1@34.417,61.4 34.424,61.406 34.424,62.138 34.685,62.399 v1(36.201,62.399) 38.927,62.399 41.726,65.198 41.726,70.101 42.425,70.799 47.127,70.799 47.419,71.091 C3.2@47.419,73.697 46.563,73.697 46.422,73.838 46.422,74.261 v1(46.354,74.329) ; R7.1@34.417,81.4 34.424,81.406 34.424,82.138 34.685,82.399 v1(36.201,82.399) 38.927,82.399 41.726,85.198 41.726,90.101 42.425,90.799 47.127,90.799 47.419,91.091 C3.2@47.419,93.697 46.563,93.697 46.422,93.838 46.422,94.261 v1(46.354,94.329) ; U1.4@44.655,5.897 44.655,4.317 44.228,3.89 44.228,3.044 C1.1@44.21,3.026 44.21,1.47 R4.2@44.33,1.35 46.728,1.35 47.55,0.528 52.452,0.528 53.757,1.833 SS1.A@53.757,2.333 53.757,6.535 54.698,7.477 P3.1@56.415,7.477 ; U1.4@44.655,25.897 44.655,24.317 44.228,23.89 44.228,23.044 C1.1@44.21,23.026 44.21,21.47 R4.2@44.33,21.35 46.728,21.35 47.55,20.528 52.452,20.528 53.757,21.833 SS1.A@53.757,22.333 53.757,26.535 54.698,27.477 P3.1@56.415,27.477 ; U1.4@44.655,45.897 44.655,44.317 44.228,43.89 44.228,43.044 C1.1@44.21,43.026 44.21,41.47 R4.2@44.33,41.35 46.728,41.35 47.55,40.528 52.452,40.528 53.757,41.833 SS1.A@53.757,42.333 53.757,46.535 54.698,47.477 P3.1@56.415,47.477 ; U1.4@44.655,65.897 44.655,64.317 44.228,63.89 44.228,63.044 C1.1@44.21,63.026 44.21,61.47 R4.2@44.33,61.35 46.728,61.35 47.55,60.528 52.452,60.528 53.757,61.833 SS1.A@53.757,62.333 53.757,66.535 54.698,67.477 P3.1@56.415,67.477 ; U1.4@44.655,85.897 44.655,84.317 44.228,83.89 44.228,83.044 C1.1@44.21,83.026 44.21,81.47 R4.2@44.33,81.35 46.728,81.35 47.55,80.528 52.452,80.528 53.757,81.833 SS1.A@53.757,82.333 53.757,86.535 54.698,87.477 P3.1@56.415,87.477 ; P3.1@56.415,7.6 56.522,7.706 v1(56.522,12.933) ; P3.1@56.415,27.6 56.522,27.706 v1(56.522,32.933) ; P3.1@56.415,47.6 56.522,47.706 v1(56.522,52.933) ; P3.1@56.415,67.6 56.522,67.706 v1(56.522,72.933) ; P3.1@56.415,87.6 56.522,87.706 v1(56.522,92.933)
  Bottom Layer w0.762: P3.1@56.415,7.6 56.415,7.477 56.415,4.784 58.26,2.939 Q1.E@64.861,2.939 64.938,3.015 72.182,3.015 J4.OUT-@72.371,3.204 ; P3.1@56.415,27.6 56.415,27.477 56.415,24.784 58.26,22.939 Q1.E@64.861,22.939 64.938,23.015 72.182,23.015 J4.OUT-@72.371,23.204 ; P3.1@56.415,47.6 56.415,47.477 56.415,44.784 58.26,42.939 Q1.E@64.861,42.939 64.938,43.015 72.182,43.015 J4.OUT-@72.371,43.204 ; P3.1@56.415,67.6 56.415,67.477 56.415,64.784 58.26,62.939 Q1.E@64.861,62.939 64.938,63.015 72.182,63.015 J4.OUT-@72.371,63.204 ; P3.1@56.415,87.6 56.415,87.477 56.415,84.784 58.26,82.939 Q1.E@64.861,82.939 64.938,83.015 72.182,83.015 J4.OUT-@72.371,83.204
Hall: R6.1 S1.1 U2.24 | length 211.5
  Top Layer w0.254: S1.1@23.216,7.399 23.219,7.395 24.019,7.395 25.203,6.211 v2(25.203,4.478) ; S1.1@23.216,27.399 23.219,27.395 24.019,27.395 25.203,26.211 v2(25.203,24.478) ; S1.1@23.216,47.399 23.219,47.395 24.019,47.395 25.203,46.211 v2(25.203,44.478) ; S1.1@23.216,67.399 23.219,67.395 24.019,67.395 25.203,66.211 v2(25.203,64.478) ; S1.1@23.216,87.399 23.219,87.395 24.019,87.395 25.203,86.211 v2(25.203,84.478) ; U2.24@46.35,10.231 48.029,10.231 48.238,10.44 48.238,10.65 47.123,11.764 v1@46.359,11.764 ; U2.24@46.35,30.231 48.029,30.231 48.238,30.44 48.238,30.65 47.123,31.764 v1@46.359,31.764 ; U2.24@46.35,50.231 48.029,50.231 48.238,50.44 48.238,50.65 47.123,51.764 v1@46.359,51.764 ; U2.24@46.35,70.231 48.029,70.231 48.238,70.44 48.238,70.65 47.123,71.764 v1@46.359,71.764 ; U2.24@46.35,90.231 48.029,90.231 48.238,90.44 48.238,90.65 47.123,91.764 v1@46.359,91.764
  Bottom Layer w0.254: v2(25.203,4.478) 25.203,3.535 26.854,1.884 31.757,1.884 34.347,4.474 39.987,4.474 41.117,5.604 41.117,10.558 42.247,11.688 46.283,11.688 v1(46.359,11.764) ; v2(25.203,24.478) 25.203,23.535 26.854,21.884 31.757,21.884 34.347,24.474 39.987,24.474 41.117,25.604 41.117,30.558 42.247,31.688 46.283,31.688 v1(46.359,31.764) ; v2(25.203,44.478) 25.203,43.535 26.854,41.884 31.757,41.884 34.347,44.474 39.987,44.474 41.117,45.604 41.117,50.558 42.247,51.688 46.283,51.688 v1(46.359,51.764) ; v2(25.203,64.478) 25.203,63.535 26.854,61.884 31.757,61.884 34.347,64.474 39.987,64.474 41.117,65.604 41.117,70.558 42.247,71.688 46.283,71.688 v1(46.359,71.764) ; v2(25.203,84.478) 25.203,83.535 26.854,81.884 31.757,81.884 34.347,84.474 39.987,84.474 41.117,85.604 41.117,90.558 42.247,91.688 46.283,91.688 v1(46.359,91.764) ; R6.1@44.214,13.722 45.775,13.722 46.336,13.161 v1@46.336,11.742 ; R6.1@44.214,33.722 45.775,33.722 46.336,33.161 v1@46.336,31.742 ; R6.1@44.214,53.722 45.775,53.722 46.336,53.161 v1@46.336,51.742 ; R6.1@44.214,73.722 45.775,73.722 46.336,73.161 v1@46.336,71.742 ; R6.1@44.214,93.722 45.775,93.722 46.336,93.161 v1@46.336,91.742
L_but: R7.2 S2.2 U2.2 | length 147.3
  Top Layer w0.254: v1(27.614,1.199) 29.014,1.199 v1(31.757,3.941) ; v1(27.614,21.199) 29.014,21.199 v1(31.757,23.941) ; v1(27.614,41.199) 29.014,41.199 v1(31.757,43.941) ; v1(27.614,61.199) 29.014,61.199 v1(31.757,63.941) ; v1(27.614,81.199) 29.014,81.199 v1(31.757,83.941) ; v3(35.617,9.478) 35.665,9.431 U2.2@37.696,9.431 ; v3(35.617,29.478) 35.665,29.431 U2.2@37.696,29.431 ; v3(35.617,49.478) 35.665,49.431 U2.2@37.696,49.431 ; v3(35.617,69.478) 35.665,69.431 U2.2@37.696,69.431 ; v3(35.617,89.478) 35.665,89.431 U2.2@37.696,89.431
  Top Layer w0.762: v2(21.216,3.899) 21.554,3.561 22.839,3.561 22.858,3.542 S2.2@22.858,3.192 ; v2(21.216,23.899) 21.554,23.561 22.839,23.561 22.858,23.542 S2.2@22.858,23.192 ; v2(21.216,43.899) 21.554,43.561 22.839,43.561 22.858,43.542 S2.2@22.858,43.192 ; v2(21.216,63.899) 21.554,63.561 22.839,63.561 22.858,63.542 S2.2@22.858,63.192 ; v2(21.216,83.899) 21.554,83.561 22.839,83.561 22.858,83.542 S2.2@22.858,83.192
  Bottom Layer w0.254: v2(21.216,3.899) 23.916,1.199 v1(27.614,1.199) 27.711,1.199 27.912,1.4 R7.2@32.817,1.4 ; v2(21.216,23.899) 23.916,21.199 v1(27.614,21.199) 27.711,21.199 27.912,21.4 R7.2@32.817,21.4 ; v2(21.216,43.899) 23.916,41.199 v1(27.614,41.199) 27.711,41.199 27.912,41.4 R7.2@32.817,41.4 ; v2(21.216,63.899) 23.916,61.199 v1(27.614,61.199) 27.711,61.199 27.912,61.4 R7.2@32.817,61.4 ; v2(21.216,83.899) 23.916,81.199 v1(27.614,81.199) 27.711,81.199 27.912,81.4 R7.2@32.817,81.4 ; v1(31.757,3.941) 35.584,7.769 35.584,9.445 v3(35.617,9.478) ; v1(31.757,23.941) 35.584,27.769 35.584,29.445 v3(35.617,29.478) ; v1(31.757,43.941) 35.584,47.769 35.584,49.445 v3(35.617,49.478) ; v1(31.757,63.941) 35.584,67.769 35.584,69.445 v3(35.617,69.478) ; v1(31.757,83.941) 35.584,87.769 35.584,89.445 v3(35.617,89.478)
NetC3_1: C3.1 U2.20 | length 87.7
  Top Layer w0.254: U2.20@46.35,7.031 46.363,7.044 48.224,7.044 v1(48.238,7.058) ; U2.20@46.35,27.031 46.363,27.044 48.224,27.044 v1(48.238,27.058) ; U2.20@46.35,47.031 46.363,47.044 48.224,47.044 v1(48.238,47.058) ; U2.20@46.35,67.031 46.363,67.044 48.224,67.044 v1(48.238,67.058) ; U2.20@46.35,87.031 46.363,87.044 48.224,87.044 v1(48.238,87.058)
  Bottom Layer w0.254: v1(48.238,7.058) 48.246,7.05 48.246,6.604 49.867,4.982 51.365,4.982 52.254,5.871 52.254,11.764 50.296,13.722 C3.1@48.816,13.722 ; v1(48.238,27.058) 48.246,27.05 48.246,26.604 49.867,24.982 51.365,24.982 52.254,25.871 52.254,31.764 50.296,33.722 C3.1@48.816,33.722 ; v1(48.238,47.058) 48.246,47.05 48.246,46.604 49.867,44.982 51.365,44.982 52.254,45.871 52.254,51.764 50.296,53.722 C3.1@48.816,53.722 ; v1(48.238,67.058) 48.246,67.05 48.246,66.604 49.867,64.982 51.365,64.982 52.254,65.871 52.254,71.764 50.296,73.722 C3.1@48.816,73.722 ; v1(48.238,87.058) 48.246,87.05 48.246,86.604 49.867,84.982 51.365,84.982 52.254,85.871 52.254,91.764 50.296,93.722 C3.1@48.816,93.722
